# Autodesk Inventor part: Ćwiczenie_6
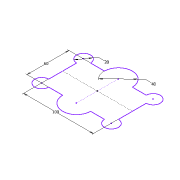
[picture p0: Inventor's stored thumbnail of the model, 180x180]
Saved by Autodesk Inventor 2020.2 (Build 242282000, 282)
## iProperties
Created: 2005-01
Part Number: Ćwiczenie_6
Document SubType Name: Modeling
Designer: F.Stasiak
Manufacturer: Standard
Standards Organization: Custom
Density: 1 g/cm^3
Material: Ogólny
Appearance: Domyślna
Manager: www.cadconsulting.pl
Company: Fabian Stasiak CAD Consulting
Author: F.Stasiak
Subject: Zbiór ćwiczeń. Autodesk Inventor 2020. Kurs podstawowy
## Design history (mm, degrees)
sketch "Szkic1"
  geometry: L1 (50, 20)-(50, -20); L2 (-50, -20)-(-50, 20); L3 (0, 30)-(0, -30); L4 (-50, 0)-(50, 0); L5 (-40, 30)-(-20, 30); L6 (20, 30)-(40, 30); L7 (40, -30)-(20, -30); L8 (-20, -30)-(-40, -30); A1 r 10 centre (-50, 30) between (-40, 30) and (-50, 20); A2 r 10 centre (50, 30) between (50, 20) and (40, 30); A3 r 10 centre (-50, -30) between (-50, -20) and (-40, -30); A4 r 10 centre (50, -30) between (40, -30) and (50, -20); A5 r 20 centre (0, 30) between (20, 30) and (-20, 30); A6 r 20 centre (0, -30) between (-20, -30) and (20, -30); 2 further points
  constraints: 16 end point, 12 point on circle, 7 parallel, 6 centre point, 4 equal radius, 3 coincident, 2 horizontal, 2 perpendicular, 1 midpoint
  dimensions: "d6" = 60 distance between parallel lines of L8 L5; "d7" = 100 distance between parallel lines of L1 L2; "d8" = 20 diameter of A1; "d9" = 40 diameter of A5
node "Korpusy bryłowe"
node "Korpusy powierzchniowe"
